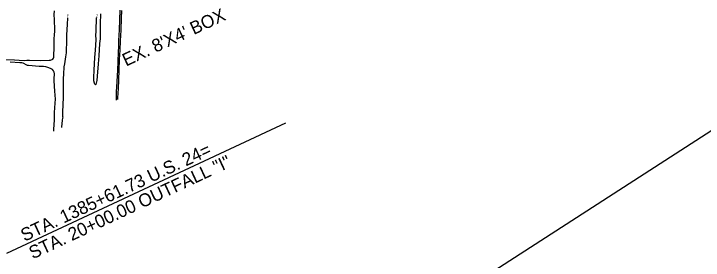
# Model space of a CAD drawing. Extents: x -310467766 to 17062430, y -322263100 to 8322522.
# Drawn here: x 1397464 to 1399466, y 572361 to 573076 of the extents above; entities that cross this region are included whole.
import ezdxf

# ---------------------------------------------------------------- set-up
doc = ezdxf.new("R2010")
doc.units = 0
for name, color, linetype in [('DT_X_Contour_Minor', 7, 'Continuous'), ('Level 19', 7, 'Continuous'), ('Level 40', 7, 'Continuous'), ('SC_Scratch1', 7, 'Continuous')]:
    doc.layers.add(name, color=color, linetype=linetype)

msp = doc.modelspace()

# ---------------------------------------------------------------- linework, layer by layer
at = {"layer": 'DT_X_Contour_Minor'}
for points in [[(1397762.7, 572825.8), (1397762.9, 572839.7), (1397762.9, 572850.9), (1397763.6, 572863.1), (1397764.6, 572879.9), (1397766.1, 572912.2), (1397767.2, 572936.5), (1397768.6, 572965.5), (1397769.2, 572980.6), (1397769.7, 572998.4), (1397771.3, 573029.2), (1397772.6, 573058.5), (1397773.7, 573086.3)], [(1397439.1, 572943.1), (1397466.3, 572942.3), (1397479.7, 572941.7), (1397495.9, 572940.8), (1397502.1, 572941.3), (1397509.7, 572941.4), (1397542.1, 572940.8), (1397567.4, 572941), (1397570.5, 572941.4), (1397573.1, 572942), (1397575.6, 572943.1), (1397577.9, 572944.7), (1397579.6, 572947.1), (1397580.6, 572950.2), (1397581, 572954), (1397581.3, 572978.4), (1397581.4, 572988.9), (1397581.2, 573003.8), (1397582.3, 573014), (1397583.5, 573026.3), (1397583.8, 573033), (1397583.8, 573039.2), (1397582.9, 573049.1), (1397582.2, 573058.5), (1397581.9, 573074), (1397582.1, 573084.5)], [(1397715.9, 573075.9), (1397715.5, 573047.2), (1397715.4, 573010.6), (1397714.9, 573002.9), (1397713.6, 572989.5), (1397711, 572953.5), (1397709.4, 572930.4), (1397706.6, 572894.9), (1397705.3, 572882.3), (1397703.6, 572874.3), (1397702.5, 572870.9), (1397701.2, 572869.6), (1397699.8, 572871.4), (1397698.5, 572875), (1397696.9, 572881.8), (1397696.6, 572886.9), (1397696.6, 572891.4), (1397697.9, 572912.2), (1397699.9, 572949.2), (1397701.5, 572970.3), (1397703.3, 573000.8), (1397703.2, 573005.9), (1397703, 573007.6), (1397702.9, 573010.9), (1397703.4, 573027.4), (1397704.9, 573063.1), (1397705.6, 573065.8)], [(1397776.9, 573085.7), (1397776.1, 573062.9), (1397774.8, 573028.6), (1397773.5, 572997), (1397772.1, 572970.2), (1397770.7, 572942.9), (1397769.6, 572913.2), (1397768.6, 572883.7), (1397767.5, 572859), (1397766, 572831.7), (1397765.8, 572827.5)], [(1397620.8, 573064.5), (1397619.3, 573044.9), (1397617.6, 573015.1), (1397617.5, 573005.3), (1397617.5, 572993.6), (1397616.8, 572970.1), (1397616.2, 572962.4), (1397614.5, 572950.7), (1397611.3, 572930.8), (1397610.1, 572922.1), (1397609.7, 572917), (1397609.9, 572913.4), (1397609.1, 572909.2), (1397608.5, 572903.8), (1397607.8, 572885.5), (1397607.4, 572860.1), (1397607.3, 572829.3), (1397607, 572816.3), (1397605.7, 572786.2), (1397606.2, 572777.8), (1397606.3, 572776.7), (1397605.4, 572773.2), (1397604.6, 572767.6), (1397603.3, 572747.1), (1397603.2, 572745.9)], [(1397580.9, 572735.4), (1397581.1, 572741.4), (1397582.7, 572767.2), (1397582.6, 572775.2), (1397582.3, 572779.5), (1397582.6, 572789.2), (1397584.1, 572816.7), (1397585.1, 572828), (1397583.9, 572851.9), (1397583, 572865.9), (1397581.3, 572882.1), (1397581.3, 572886.9), (1397582.1, 572901.5), (1397581.6, 572906.3), (1397580, 572910.6), (1397576.4, 572914.5), (1397570.5, 572917.6), (1397563.6, 572920), (1397557.4, 572921.7), (1397550.4, 572922.8), (1397538, 572923.3), (1397507.5, 572925.5), (1397504.3, 572925.9), (1397501.8, 572926.8), (1397491.2, 572932.7), (1397487.5, 572933.5), (1397481.6, 572934.1), (1397453.7, 572936)]]:
    msp.add_lwpolyline(points, dxfattribs=at)
at = {"layer": 'Level 40'}
msp.add_line((1397443.7, 572381.8), (1398254.3, 572759.8), dxfattribs=at)
at = {"layer": 'SC_Scratch1'}
msp.add_lwpolyline([(1392212.4, 573822.1), (1393676.3, 570715.4), (1396857.5, 571041.4), (1399761.2, 572912.7), (1399601.4, 573251.9), (1400998.4, 575913.7), (1400551.7, 577289.3)], close=True, dxfattribs=at)

# ---------------------------------------------------------------- texts
at = {"layer": 'Level 19'}
for rotation, p in [(87.5938, (1397622.9, 573065.1)), (82.1965, (1397708.2, 573066.2))]:
    msp.add_text('718', height=4, rotation=rotation, dxfattribs=at).set_placement(p)
at = {"layer": 'Level 40'}
for s, p in [("EX. 8'X4' BOX", (1397790.3, 572922.5)), ('STA. 1385+61.73 U.S. 24=', (1397495.4, 572414.4)), ('STA. 20+00.00 OUTFALL "I"', (1397519.2, 572363.4))]:
    msp.add_text(s, height=37.5, rotation=25, dxfattribs=at).set_placement(p)

doc.saveas('drawing.dxf')
